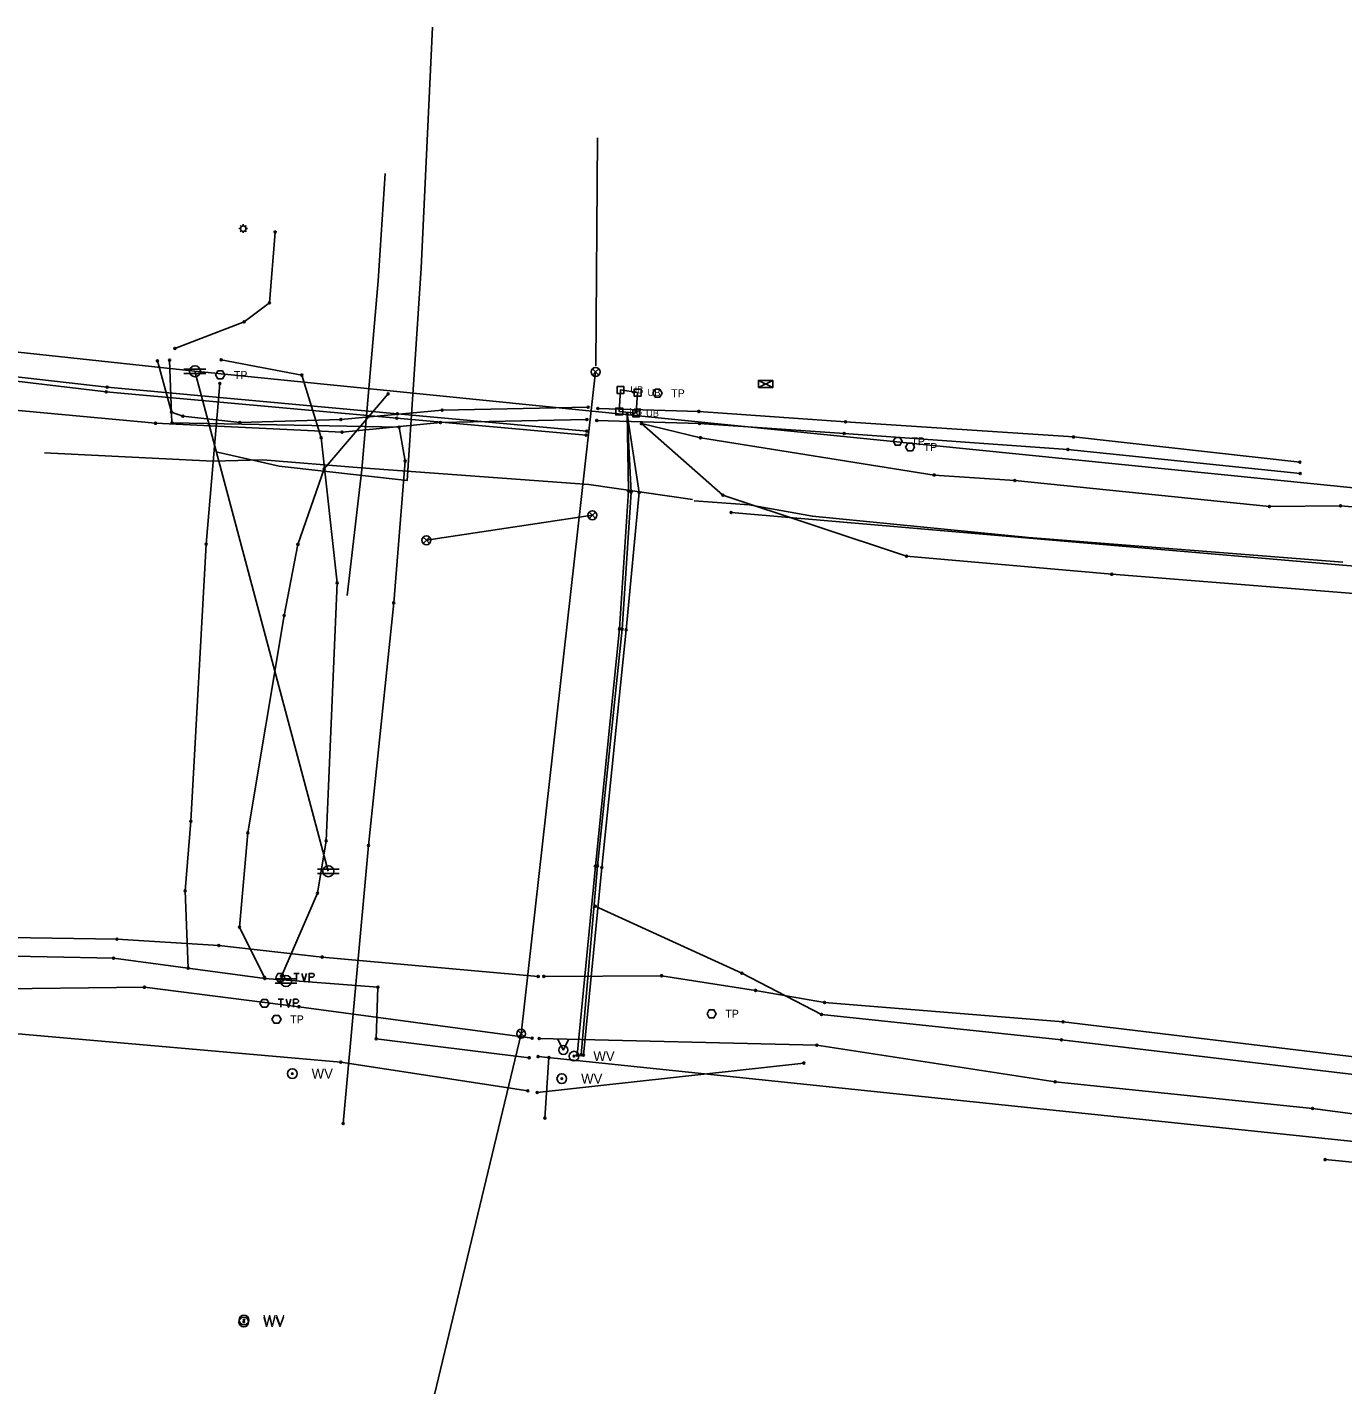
# Model space of a CAD drawing. Extents: x 20500343 to 20505311, y 7953484 to 7954193.
# Drawn here: x 20501663.2 to 20501927.3, y 7953765.2 to 7954037.8 of the extents above; entities that cross this region are included whole.
import ezdxf

# ---------------------------------------------------------------- set-up
doc = ezdxf.new("R2010")
doc.units = 0
for name, color, linetype in [('C-PROP-LINE-LOT', 7, 'Continuous'), ('V-ANNO-BNDY', 7, 'Continuous'), ('V-ANNO-NOTE', 7, 'Continuous'), ('V-CTRL-HVPT', 7, 'Continuous'), ('V-MON-FND', 7, 'Continuous'), ('V-SITE-FENC', 7, 'Continuous'), ('V-SSWR-STRC', 7, 'Continuous'), ('VF-NODE-MISC', 7, 'Continuous')]:
    doc.layers.add(name, color=color, linetype=linetype)

msp = doc.modelspace()

# ---------------------------------------------------------------- linework, layer by layer
at = {"layer": 'C-PROP-LINE-LOT'}
msp.add_line((20501777.39, 7953969.82), (20501777.74, 7954015.56), dxfattribs=at)
for points in [[(20501744.62, 7954037.81), (20501742.35, 7953989.4), (20501739.51, 7953946.77), (20501713.85, 7953949.66), (20501701.43, 7953952.46)], [(20501727.48, 7953923.73), (20501730.4, 7953949.03), (20501733.7, 7953986.9), (20501735.07, 7954008.45)], [(20501316.97, 7954003.56), (20501331.13, 7953995.08), (20501366.04, 7953982.93), (20501414.04, 7953978.62), (20501439.53, 7953975.27), (20501515.39, 7953971.55), (20501543.03, 7953969.36), (20501590.25, 7953966.08), (20501636.14, 7953963.16), (20501689.01, 7953958.28), (20501726.44, 7953956.52), (20501746.18, 7953958.43), (20501775.61, 7953959.04)], [(20500996.43, 7953915.71), (20500994.86, 7953939.31), (20500993.84, 7953971.13), (20500992.21, 7953991.99), (20500998.39, 7953997.86), (20501033.4, 7953996.49), (20501087.77, 7953993.38), (20501147.66, 7953991.76), (20501204.37, 7953990.78), (20501258.68, 7953993.69), (20501291.5, 7953992.96), (20501367.31, 7953988.1), (20501415.06, 7953984.51), (20501437.58, 7953981.75), (20501512.96, 7953981.34), (20501564.43, 7953975.75), (20501615.72, 7953972.77), (20501679.29, 7953965.51), (20501737.55, 7953960.19), (20501775.55, 7953956.71)], [(20500997.07, 7953915.68), (20500995.89, 7953938.94), (20500994.71, 7953971.1), (20500993, 7953991.18), (20500998.42, 7953997.06), (20501033.28, 7953995.67), (20501087.63, 7953992.68), (20501147.58, 7953990.88), (20501204.03, 7953989.96), (20501258.58, 7953992.74), (20501291.52, 7953992.27), (20501367.1, 7953987.19), (20501414.72, 7953983.8), (20501438.34, 7953980.22), (20501512.8, 7953980.63), (20501564.51, 7953974.63), (20501615.49, 7953972.13), (20501679.12, 7953964.62), (20501737.42, 7953959.32), (20501775.43, 7953955.89)], [(20501713.01, 7953996.68), (20501711.87, 7953982.44), (20501706.82, 7953978.65), (20501692.89, 7953973.31)], [(20501461.7, 7953994.07), (20501696.91, 7953968.73), (20501941.48, 7953944.15)], [(20501689.37, 7953970.81), (20501692.2, 7953960.52), (20501694.48, 7953959.7), (20501705.91, 7953958.43), (20501726.2, 7953959.04), (20501746.52, 7953960.9), (20501775.86, 7953961.51)], [(20501726.68, 7953817.69), (20501731.75, 7953873.51), (20501736.81, 7953922.23), (20501739.12, 7953950.71), (20501737.89, 7953957.48), (20501692.31, 7953958.35), (20501691.84, 7953970.94)], [(20501714.28, 7953847.29), (20501721.51, 7953863.97), (20501723.25, 7953874.47), (20501725.49, 7953926.22), (20501722.27, 7953955.34), (20501718.35, 7953967.97), (20501702.18, 7953971)], [(20501696.91, 7953968.73), (20501723.69, 7953868.35)], [(20501777.33, 7953968.6), (20501762.4, 7953835.72), (20501712.2, 7953626.83)], [(20501701.93, 7953966.29), (20501699.17, 7953934.01), (20501696.1, 7953878.37), (20501694.95, 7953864.44), (20501695.55, 7953848.89)], [(20501735.69, 7953964.18), (20501722.87, 7953949.15), (20501717.6, 7953933.98), (20501714.81, 7953919.71), (20501707.53, 7953876.05), (20501705.88, 7953857.12), (20501710.87, 7953847.05)], [(20501777.78, 7953961.27), (20501798.06, 7953960.68), (20501827.5, 7953958.56), (20501873.27, 7953955.53), (20501918.72, 7953950.49)], [(20501773.65, 7953831.41), (20501777.29, 7953869.38), (20501782.14, 7953916.99), (20501783.92, 7953944.74), (20501783.69, 7953960.19)], [(20501774.46, 7953831.5), (20501777.74, 7953869.44), (20501782.67, 7953916.97), (20501784.47, 7953944.47), (20501783.69, 7953960.19)], [(20501774.9, 7953831.45), (20501778.57, 7953869.09), (20501783.47, 7953916.83), (20501786.1, 7953944.37), (20501783.69, 7953960.19)], [(20501777.56, 7953958.86), (20501798.2, 7953958.25), (20501827.24, 7953956.23), (20501872.14, 7953953.03), (20501918.79, 7953948.19)], [(20501786.53, 7953958.21), (20501802.89, 7953943.86), (20501839.77, 7953931.6), (20501880.96, 7953927.96), (20502018.29, 7953917.03), (20502077.19, 7953911.09), (20502142.41, 7953905.45), (20502199.08, 7953901.71), (20502241.51, 7953895.28), (20502292.25, 7953890.73), (20502324.65, 7953886.92), (20502369.24, 7953880.93), (20502409.05, 7953877.23), (20502443.31, 7953873.2), (20502481.36, 7953863.28), (20502512.4, 7953858.05), (20502594.55, 7953857.22)], [(20501786.53, 7953958.21), (20501798.37, 7953955.39), (20501845.31, 7953947.9), (20501861.48, 7953946.79), (20501912.59, 7953941.56), (20501926.87, 7953941.71), (20502019.52, 7953933.84), (20502080.36, 7953927.46), (20502107.02, 7953924.08), (20502144.15, 7953919.15), (20502174.11, 7953916.47), (20502211.46, 7953910.85), (20502243.75, 7953903.07), (20502293.11, 7953894.8), (20502325.39, 7953891.51), (20502370.1, 7953885.96), (20502409.42, 7953880.13), (20502443.48, 7953874.15), (20502481.41, 7953864.06), (20502512.42, 7953858.66), (20502594.72, 7953856.58)], [(20501666.69, 7953952.38), (20501700.53, 7953950.69), (20501710.54, 7953950.92), (20501730.28, 7953949.37), (20501775.95, 7953946.01), (20501796.82, 7953942.97)], [(20501797.14, 7953942.74), (20501808.15, 7953941.88), (20501820.85, 7953939.62), (20501864.23, 7953935.32), (20501927.31, 7953930.39)], [(20501743.38, 7953934.81), (20501776.69, 7953939.81)], [(20501804.54, 7953940.37), (20502005.09, 7953923.1), (20502111.03, 7953911.19), (20502201.18, 7953904.98), (20502309.45, 7953894.18), (20502395.03, 7953885.06)], [(20500998.83, 7953913.68), (20501022.94, 7953911.59), (20501056.17, 7953908.34), (20501118.67, 7953904.16), (20501155.66, 7953902.37), (20501207.31, 7953899.83), (20501244.54, 7953898.43), (20501286.93, 7953897.81), (20501305.79, 7953896.3), (20501317.66, 7953895.88), (20501451.4, 7953874.84), (20501522.75, 7953865.03), (20501559.04, 7953858.38), (20501592.55, 7953848.31), (20501608.82, 7953843.84), (20501626.02, 7953848.37), (20501659.58, 7953855.08), (20501681.27, 7953854.69), (20501701.7, 7953853.44), (20501722.46, 7953851.13), (20501765.84, 7953847.22)], [(20501263.02, 7953904.3), (20501263.23, 7953899.59), (20501267.6, 7953894.11), (20501302.56, 7953892.31), (20501415.59, 7953889.07), (20501446.52, 7953886.98), (20501469.46, 7953879.66), (20501523.96, 7953857.45), (20501561.35, 7953852.73), (20501613.91, 7953852.27), (20501680.57, 7953850.9), (20501710.93, 7953846.81), (20501733.66, 7953845.08), (20501733.32, 7953834.72), (20501764.02, 7953830.92)], [(20501777.25, 7953861.34), (20501806.68, 7953847.91), (20501822.69, 7953839.61)], [(20501766.93, 7953847.25), (20501790.58, 7953847.38), (20501809.46, 7953844.44), (20501823.3, 7953842.02), (20501871.18, 7953838.12)], [(20501489.92, 7953842.63), (20501525.91, 7953842.83), (20501570.93, 7953842.53), (20501621.81, 7953838.23), (20501652.93, 7953844.67), (20501686.76, 7953845.05), (20501717.8, 7953841.16), (20501764.61, 7953834.86)], [(20501480.62, 7953829.39), (20501493.47, 7953831.21), (20501531.23, 7953830.89), (20501561.61, 7953833.31), (20501593.25, 7953840.01), (20501618.52, 7953841.58), (20501659.08, 7953835.94), (20501726.17, 7953830)], [(20501822.69, 7953839.61), (20501870.85, 7953834.49), (20501955.49, 7953824.45), (20502075.53, 7953814.96), (20502170.68, 7953806.48), (20502238.89, 7953800.97), (20502334.58, 7953792.75), (20502432.59, 7953781.98), (20502508.31, 7953776.06), (20502531.87, 7953776.49), (20502581.28, 7953773.17)], [(20501871.18, 7953838.12), (20501950.16, 7953828.62), (20502076.03, 7953818.34), (20502154.77, 7953811.13), (20502239.61, 7953803.57), (20502335.63, 7953794.91), (20502433.27, 7953786.61), (20502509.73, 7953784.12), (20502531.75, 7953782.62), (20502583.58, 7953780.86)], [(20501766.01, 7953834.76), (20501821.75, 7953833.43), (20501869.61, 7953826.07), (20501921.27, 7953820.74), (20501975.38, 7953813.59), (20502027.18, 7953809.28), (20502096.84, 7953802.19), (20502149.48, 7953798.41), (20502206.76, 7953791.49), (20502246.02, 7953783), (20502332.45, 7953784.05), (20502423.49, 7953775.99), (20502457.77, 7953772.43), (20502468.01, 7953774.31), (20502490.69, 7953772.12), (20502532.01, 7953768.89), (20502567.5, 7953767.25)], [(20501765.8, 7953831.13), (20501934, 7953813.62), (20501986.76, 7953807.7), (20502096.89, 7953796.9), (20502224.25, 7953788.94), (20502278.96, 7953784.08), (20502408.88, 7953781.44), (20502417.83, 7953784.37), (20502465.46, 7953783.06), (20502531.65, 7953780.57), (20502583.55, 7953776.2)], [(20501726.17, 7953830), (20501763.73, 7953824.24)], [(20501765.61, 7953823.95), (20501819.16, 7953829.85)], [(20501923.78, 7953810.45), (20501976.29, 7953805.33), (20502027.19, 7953800.79), (20502097.04, 7953794.03), (20502148.61, 7953790.06), (20502191.57, 7953787.56), (20502246.17, 7953780.88), (20502423.34, 7953773.23), (20502457.56, 7953769.95), (20502471.39, 7953769.52), (20502491.18, 7953768.99), (20502531.55, 7953766.92), (20502567.17, 7953761.38)]]:
    msp.add_lwpolyline(points, dxfattribs=at)
at = {"layer": 'V-ANNO-BNDY'}
msp.add_lwpolyline([(20501767.98, 7953830.94), (20501767.18, 7953818.79)], dxfattribs=at)
at = {"layer": 'V-ANNO-NOTE'}
for centre in [(20501713.01, 7953996.68), (20501711.87, 7953982.44), (20501706.82, 7953978.65), (20501692.89, 7953973.31), (20501689.37, 7953970.81), (20501691.84, 7953970.94), (20501702.18, 7953971), (20501701.93, 7953966.29), (20501718.35, 7953967.97), (20501679.12, 7953964.62), (20501679.29, 7953965.51), (20501735.69, 7953964.18), (20501746.52, 7953960.9), (20501775.86, 7953961.51), (20501777.78, 7953961.27), (20501689.01, 7953958.28), (20501692.2, 7953960.52), (20501692.31, 7953958.35), (20501694.48, 7953959.7), (20501705.91, 7953958.43), (20501726.2, 7953959.04), (20501737.42, 7953959.32), (20501737.55, 7953960.19), (20501746.18, 7953958.43), (20501775.61, 7953959.04), (20501777.56, 7953958.86), (20501783.69, 7953960.19), (20501783.69, 7953960.19), (20501783.69, 7953960.19), (20501786.53, 7953958.21), (20501786.53, 7953958.21), (20501798.06, 7953960.68), (20501798.2, 7953958.25), (20501827.5, 7953958.56), (20501722.27, 7953955.34), (20501726.44, 7953956.52), (20501737.89, 7953957.48), (20501775.43, 7953955.89), (20501775.55, 7953956.71), (20501798.37, 7953955.39), (20501827.24, 7953956.23), (20501873.27, 7953955.53), (20501872.14, 7953953.03), (20501739.12, 7953950.71), (20501918.72, 7953950.49), (20501722.87, 7953949.15), (20501845.31, 7953947.9), (20501918.79, 7953948.19), (20501783.92, 7953944.74), (20501784.47, 7953944.47), (20501786.1, 7953944.37), (20501861.48, 7953946.79), (20501802.89, 7953943.86), (20501926.87, 7953941.71), (20501804.54, 7953940.37), (20501912.59, 7953941.56), (20501699.17, 7953934.01), (20501717.6, 7953933.98), (20501839.77, 7953931.6), (20501725.49, 7953926.22), (20501880.96, 7953927.96), (20501736.81, 7953922.23), (20501714.81, 7953919.71), (20501782.14, 7953916.99), (20501782.67, 7953916.97), (20501783.47, 7953916.83), (20501696.1, 7953878.37), (20501707.53, 7953876.05), (20501723.25, 7953874.47), (20501731.75, 7953873.51), (20501777.29, 7953869.38), (20501777.74, 7953869.44), (20501778.57, 7953869.09), (20501694.95, 7953864.44), (20501721.51, 7953863.97), (20501777.25, 7953861.34), (20501681.27, 7953854.69), (20501705.88, 7953857.12), (20501701.7, 7953853.44), (20501680.57, 7953850.9), (20501722.46, 7953851.13), (20501695.55, 7953848.89), (20501710.87, 7953847.05), (20501710.93, 7953846.81), (20501714.28, 7953847.29), (20501765.84, 7953847.22), (20501766.93, 7953847.25), (20501790.58, 7953847.38), (20501806.68, 7953847.91), (20501686.76, 7953845.05), (20501733.66, 7953845.08), (20501809.46, 7953844.44), (20501717.8, 7953841.16), (20501823.3, 7953842.02), (20501822.69, 7953839.61), (20501822.69, 7953839.61), (20501871.18, 7953838.12), (20501871.18, 7953838.12), (20501733.32, 7953834.72), (20501764.61, 7953834.86), (20501766.01, 7953834.76), (20501821.75, 7953833.43), (20501870.85, 7953834.49), (20501726.17, 7953830), (20501726.17, 7953830), (20501764.02, 7953830.92), (20501765.8, 7953831.13), (20501767.98, 7953830.94), (20501773.65, 7953831.41), (20501774.46, 7953831.5), (20501774.9, 7953831.45), (20501819.16, 7953829.85), (20501869.61, 7953826.07), (20501763.73, 7953824.24), (20501765.61, 7953823.95), (20501921.27, 7953820.74), (20501726.68, 7953817.69), (20501767.18, 7953818.79), (20501923.78, 7953810.45)]:
    msp.add_circle(centre, 0.2, dxfattribs=at)
at = {"layer": 'V-CTRL-HVPT'}
for p, q in [((20501705.74, 7953997.36), (20501706.07, 7953997.36)), ((20501706, 7953997.97), (20501706.23, 7953997.74)), ((20501706, 7953996.74), (20501706.23, 7953996.97)), ((20501706.61, 7953998.23), (20501706.61, 7953997.9)), ((20501706.61, 7953996.82), (20501706.61, 7953996.49)), ((20501706.99, 7953997.74), (20501707.22, 7953997.97)), ((20501706.99, 7953996.97), (20501707.22, 7953996.74)), ((20501707.15, 7953997.36), (20501707.48, 7953997.36)), ((20501694.71, 7953969.17), (20501699.11, 7953969.17)), ((20501694.71, 7953968.29), (20501699.11, 7953968.29)), ((20501721.49, 7953868.79), (20501725.89, 7953868.79)), ((20501721.49, 7953867.91), (20501725.89, 7953867.91)), ((20501712.99, 7953846.75), (20501717.39, 7953846.75)), ((20501712.99, 7953845.87), (20501717.39, 7953845.87))]:
    msp.add_line(p, q, dxfattribs=at)
for centre, radius in [((20501706.61, 7953997.36), 0.543), ((20501696.91, 7953968.73), 1.1), ((20501723.69, 7953868.35), 1.1), ((20501715.19, 7953846.31), 1.1)]:
    msp.add_circle(centre, radius, dxfattribs=at)
at = {"layer": 'V-MON-FND'}
for points in [[(20501701.07, 7953967.99), (20501701.52, 7953968.78), (20501702.44, 7953968.78), (20501702.89, 7953967.99), (20501702.44, 7953967.2), (20501701.52, 7953967.2), (20501701.07, 7953967.99)], [(20501788.86, 7953964.31), (20501789.31, 7953965.1), (20501790.23, 7953965.1), (20501790.68, 7953964.31), (20501790.23, 7953963.52), (20501789.31, 7953963.52), (20501788.86, 7953964.31)], [(20501837.06, 7953954.66), (20501837.51, 7953955.46), (20501838.43, 7953955.46), (20501838.88, 7953954.66), (20501838.43, 7953953.87), (20501837.51, 7953953.87), (20501837.06, 7953954.66)], [(20501839.56, 7953953.51), (20501840.01, 7953954.3), (20501840.93, 7953954.3), (20501841.38, 7953953.51), (20501840.93, 7953952.72), (20501840.01, 7953952.72), (20501839.56, 7953953.51)], [(20501712.38, 7953838.62), (20501712.83, 7953839.41), (20501713.75, 7953839.41), (20501714.2, 7953838.62), (20501713.75, 7953837.83), (20501712.83, 7953837.83), (20501712.38, 7953838.62)], [(20501799.72, 7953839.74), (20501800.17, 7953840.53), (20501801.09, 7953840.53), (20501801.54, 7953839.74), (20501801.09, 7953838.95), (20501800.17, 7953838.95), (20501799.72, 7953839.74)]]:
    msp.add_lwpolyline(points, dxfattribs=at)
msp.add_lwpolyline([(20501785.77, 7953964.44), (20501785.48, 7953960.29), (20501782.09, 7953960.65), (20501782.34, 7953964.97)], close=True, dxfattribs=at)
msp.add_lwpolyline([(20501785.77, 7953964.44), (20501785.48, 7953960.29), (20501782.09, 7953960.65), (20501782.34, 7953964.97)], close=True, dxfattribs=at)
at = {"layer": 'V-SITE-FENC'}
for points in [[(20501782.34, 7953964.28), (20501782.34, 7953964.28), (20501783.03, 7953964.28), (20501783.03, 7953965.66), (20501781.65, 7953965.66), (20501781.65, 7953964.28), (20501782.34, 7953964.28)], [(20501785.77, 7953963.76), (20501785.77, 7953963.76), (20501786.46, 7953963.76), (20501786.46, 7953965.13), (20501785.08, 7953965.13), (20501785.08, 7953963.76), (20501785.77, 7953963.76)], [(20501782.09, 7953959.96), (20501782.09, 7953959.96), (20501782.78, 7953959.96), (20501782.78, 7953961.33), (20501781.4, 7953961.33), (20501781.4, 7953959.96), (20501782.09, 7953959.96)], [(20501785.48, 7953959.6), (20501785.48, 7953959.6), (20501786.17, 7953959.6), (20501786.17, 7953960.97), (20501784.79, 7953960.97), (20501784.79, 7953959.6), (20501785.48, 7953959.6)]]:
    msp.add_lwpolyline(points, dxfattribs=at)
at = {"layer": 'V-SSWR-STRC'}
for points in [[(20501776.69, 7953967.97), (20501777.33, 7953968.6), (20501776.69, 7953969.24)], [(20501777.97, 7953969.24), (20501777.33, 7953968.6), (20501777.97, 7953967.97)], [(20501810.02, 7953965.44), (20501812.9, 7953966.88), (20501812.9, 7953965.44), (20501810.02, 7953966.88)], [(20501776.05, 7953939.17), (20501776.69, 7953939.81), (20501776.05, 7953940.45)], [(20501777.33, 7953940.45), (20501776.69, 7953939.81), (20501777.33, 7953939.17)], [(20501742.74, 7953934.18), (20501743.38, 7953934.81), (20501742.74, 7953935.45)], [(20501744.02, 7953935.45), (20501743.38, 7953934.81), (20501744.02, 7953934.18)], [(20501761.76, 7953835.08), (20501762.4, 7953835.72), (20501761.76, 7953836.35)], [(20501763.04, 7953836.35), (20501762.4, 7953835.72), (20501763.04, 7953835.08)]]:
    msp.add_lwpolyline(points, dxfattribs=at)
msp.add_lwpolyline([(20501810.02, 7953965.44), (20501810.02, 7953966.88), (20501812.9, 7953966.88), (20501812.9, 7953965.44)], close=True, dxfattribs=at)
for centre, radius in [((20501773.02, 7953831.23), 0.971), ((20501773.02, 7953831.23), 0.162), ((20501716.46, 7953827.72), 0.971), ((20501716.46, 7953827.72), 0.162), ((20501770.56, 7953826.72), 0.971), ((20501770.56, 7953826.72), 0.162), ((20501706.72, 7953777.84), 0.971), ((20501706.76, 7953778.25), 0.971), ((20501706.76, 7953778.25), 0.162), ((20501706.72, 7953777.84), 0.162)]:
    msp.add_circle(centre, radius, dxfattribs=at)
for centre, start, end in [((20501777.33, 7953968.6), 135, 225), ((20501777.33, 7953968.6), 45, 135), ((20501777.33, 7953968.6), 315, 45), ((20501777.33, 7953968.6), 225, 315), ((20501776.69, 7953939.81), 135, 225), ((20501776.69, 7953939.81), 45, 135), ((20501776.69, 7953939.81), 225, 315), ((20501776.69, 7953939.81), 315, 45), ((20501743.38, 7953934.81), 135, 225), ((20501743.38, 7953934.81), 45, 135), ((20501743.38, 7953934.81), 225, 315), ((20501743.38, 7953934.81), 315, 45), ((20501762.4, 7953835.72), 135, 225), ((20501762.4, 7953835.72), 45, 135), ((20501762.4, 7953835.72), 315, 45), ((20501762.4, 7953835.72), 225, 315)]:
    msp.add_arc(centre, 0.899, start, end, dxfattribs=at)
at = {"layer": 'VF-NODE-MISC'}
for p, q in [((20501713.12, 7953847.03), (20501713.58, 7953847.82)), ((20501713.58, 7953846.24), (20501713.12, 7953847.03)), ((20501713.58, 7953847.82), (20501714.49, 7953847.82)), ((20501714.49, 7953847.82), (20501714.95, 7953847.03)), ((20501714.95, 7953847.03), (20501714.49, 7953846.24)), ((20501716.78, 7953847.85), (20501717.83, 7953847.85)), ((20501717.3, 7953847.85), (20501717.3, 7953846.26)), ((20501714.49, 7953846.24), (20501713.58, 7953846.24)), ((20501709.96, 7953841.83), (20501710.42, 7953842.62)), ((20501710.42, 7953841.04), (20501709.96, 7953841.83)), ((20501710.42, 7953842.62), (20501711.33, 7953842.62)), ((20501711.33, 7953841.04), (20501710.42, 7953841.04)), ((20501711.33, 7953842.62), (20501711.79, 7953841.83)), ((20501711.79, 7953841.83), (20501711.33, 7953841.04)), ((20501713.62, 7953842.65), (20501714.67, 7953842.65)), ((20501714.14, 7953842.65), (20501714.14, 7953841.06)), ((20501769.78, 7953834.61), (20501770.86, 7953832.46)), ((20501770.86, 7953832.46), (20501771.94, 7953834.61))]:
    msp.add_line(p, q, dxfattribs=at)
for points in [[(20501719.34, 7953847.85), (20501718.85, 7953846.26), (20501718.36, 7953847.85)], [(20501719.87, 7953846.26), (20501719.87, 7953847.85), (20501720.59, 7953847.85), (20501720.85, 7953847.6), (20501720.85, 7953847.34), (20501720.59, 7953847.07), (20501719.87, 7953847.07)], [(20501716.18, 7953842.65), (20501715.69, 7953841.06), (20501715.2, 7953842.65)], [(20501716.71, 7953841.06), (20501716.71, 7953842.65), (20501717.43, 7953842.65), (20501717.69, 7953842.4), (20501717.69, 7953842.14), (20501717.43, 7953841.87), (20501716.71, 7953841.87)]]:
    msp.add_lwpolyline(points, dxfattribs=at)
msp.add_circle((20501770.86, 7953832.46), 0.897, dxfattribs=at)

# ---------------------------------------------------------------- texts
at = {"layer": 'V-MON-FND'}
for p in [(20501704.72, 7953967.19), (20501792.51, 7953963.51), (20501840.71, 7953953.86), (20501843.21, 7953952.71), (20501716.03, 7953837.82), (20501803.37, 7953838.94)]:
    msp.add_text('TP', height=1.599, dxfattribs=at).set_placement(p)
at = {"layer": 'V-SITE-FENC'}
for p in [(20501784.33, 7953964.29), (20501787.76, 7953963.76), (20501784.08, 7953959.96), (20501787.47, 7953959.61)]:
    msp.add_text('UB', height=1.399, dxfattribs=at).set_placement(p)
at = {"layer": 'V-SSWR-STRC'}
for p in [(20501776.9, 7953830.24), (20501720.34, 7953826.73), (20501774.44, 7953825.73), (20501710.6, 7953776.85), (20501710.64, 7953777.26)]:
    msp.add_text('WV', height=1.982, dxfattribs=at).set_placement(p)

doc.saveas('drawing.dxf')
